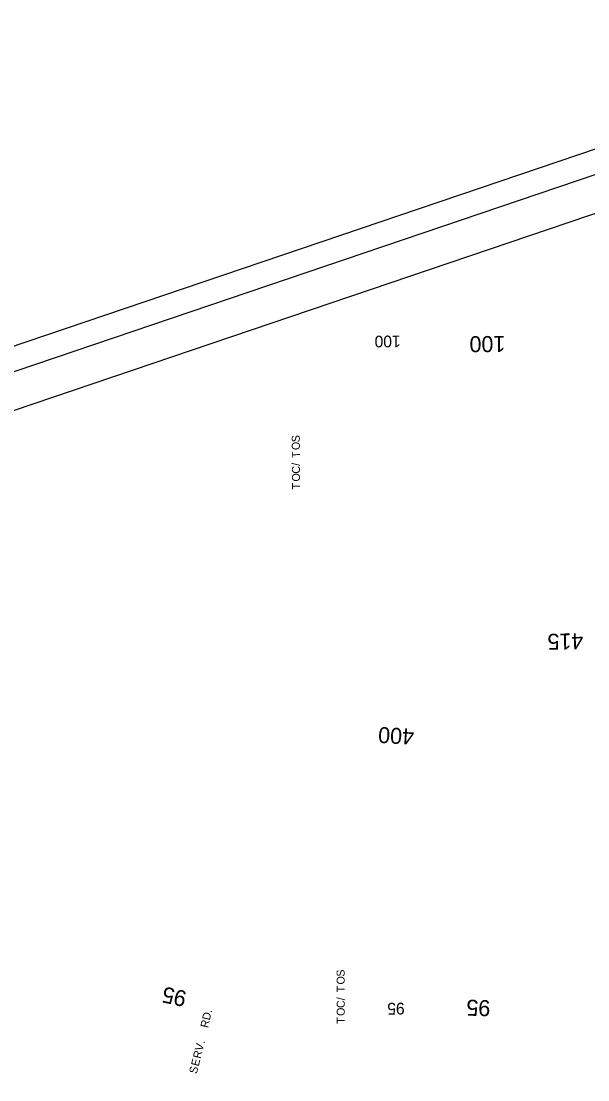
# Model space of a CAD drawing. Extents: x 2150080 to 2151795, y 143169 to 145259.
# Drawn here: x 2150504 to 2150929, y 144466 to 145259 of the extents above; entities that cross this region are included whole.
import ezdxf

# ---------------------------------------------------------------- set-up
doc = ezdxf.new("R2010")
doc.units = 0
for name, color, linetype in [('EX_Align_Sta', 7, 'Continuous'), ('PR_Align_Ramp_B_Sta', 7, 'Continuous'), ('PR_Align_Ramp_H_Sta', 7, 'Continuous'), ('PR_Align_Service_B_Sta', 7, 'Continuous'), ('PR_Align_Service_C_Label', 7, 'Continuous'), ('PR_Align_Service_C_Sta', 7, 'Continuous'), ('PR_Grading_Txt', 7, 'Continuous'), ('SHT_Plot_Shape_Full', 7, 'Continuous'), ('SHT_Plot_Shape_Half', 7, 'Continuous'), ('SHT_Sheet_Border', 7, 'Continuous')]:
    doc.layers.add(name, color=color, linetype=linetype)

msp = doc.modelspace()

# ---------------------------------------------------------------- linework, layer by layer
at = {"layer": 'SHT_Plot_Shape_Full'}
msp.add_lwpolyline([(2150658.42, 143168.88), (2150080.15, 144873.46), (2151216.53, 145258.98), (2151794.81, 143554.39)], close=True, dxfattribs=at)
at = {"layer": 'SHT_Plot_Shape_Half'}
msp.add_lwpolyline([(2150671.18, 143259.66), (2150125.03, 144869.55), (2151166.72, 145222.94), (2151712.87, 143613.05)], close=True, dxfattribs=at)
at = {"layer": 'SHT_Sheet_Border'}
msp.add_lwpolyline([(2151151.88, 145188.86), (2151657.87, 143697.35), (2150663.53, 143360.03), (2150157.54, 144851.54)], close=True, dxfattribs=at)

# ---------------------------------------------------------------- texts
at = {"layer": 'EX_Align_Sta'}
for s, p in [('100', (2150788.5, 145023.41)), ('95', (2150791.5, 144523.41))]:
    msp.add_text(s, height=8.75, rotation=180.34426, dxfattribs=at).set_placement(p)
at = {"layer": 'PR_Align_Ramp_B_Sta'}
msp.add_text('400', height=12, rotation=176.56481, dxfattribs=at).set_placement((2150798.85, 144728.62))
at = {"layer": 'PR_Align_Ramp_H_Sta'}
msp.add_text('415', height=12, rotation=181.16271, dxfattribs=at).set_placement((2150925.14, 144800.4))
at = {"layer": 'PR_Align_Service_B_Sta'}
for s, rotation, p in [('100', 180.34425, (2150866.82, 145023.11)), ('95', 178.41568, (2150855.82, 144525.27))]:
    msp.add_text(s, height=12, rotation=rotation, dxfattribs=at).set_placement(p)
at = {"layer": 'PR_Align_Service_C_Label'}
for s, rotation, p in [('R', 76.99967, (2150644.29, 144504.21)), ('D', 77.23596, (2150645.61, 144509.95)), ('.', 77.47224, (2150646.92, 144515.7)), ('.', 76.52288, (2150641.54, 144492.64)), ('R', 76.05032, (2150638.72, 144481.19)), ('V', 76.2866, (2150640.14, 144486.91)), ('E', 75.81403, (2150637.27, 144475.48)), ('S', 75.57775, (2150635.8, 144469.77))]:
    msp.add_text(s, height=6, rotation=rotation, dxfattribs=at).set_placement(p)
at = {"layer": 'PR_Align_Service_C_Sta'}
msp.add_text('95', height=12, rotation=167.58076, dxfattribs=at).set_placement((2150628.98, 144531.86))
at = {"layer": 'PR_Grading_Txt'}
for s, rotation, p in [('S', 90.34377, (2150713, 144943.49)), ('O', 90.34377, (2150713.04, 144937.6)), ('T', 90.34407, (2150713.07, 144931.7)), ('/', 90.34377, (2150713.11, 144925.81)), ('C', 90.34377, (2150713.14, 144919.91)), ('O', 90.32076, (2150713.18, 144914.02)), ('T', 90.34377, (2150713.21, 144908.12)), ('S', 90.56318, (2150746.61, 144543.01)), ('O', 90.56318, (2150746.66, 144537.12)), ('T', 89.8542, (2150746.68, 144531.22)), ('/', 89.8542, (2150746.67, 144525.33)), ('O', 89.8542, (2150746.64, 144513.54)), ('C', 89.8542, (2150746.65, 144519.44)), ('T', 89.8542, (2150746.62, 144507.65))]:
    msp.add_text(s, height=6, rotation=rotation, dxfattribs=at).set_placement(p)

doc.saveas('drawing.dxf')
